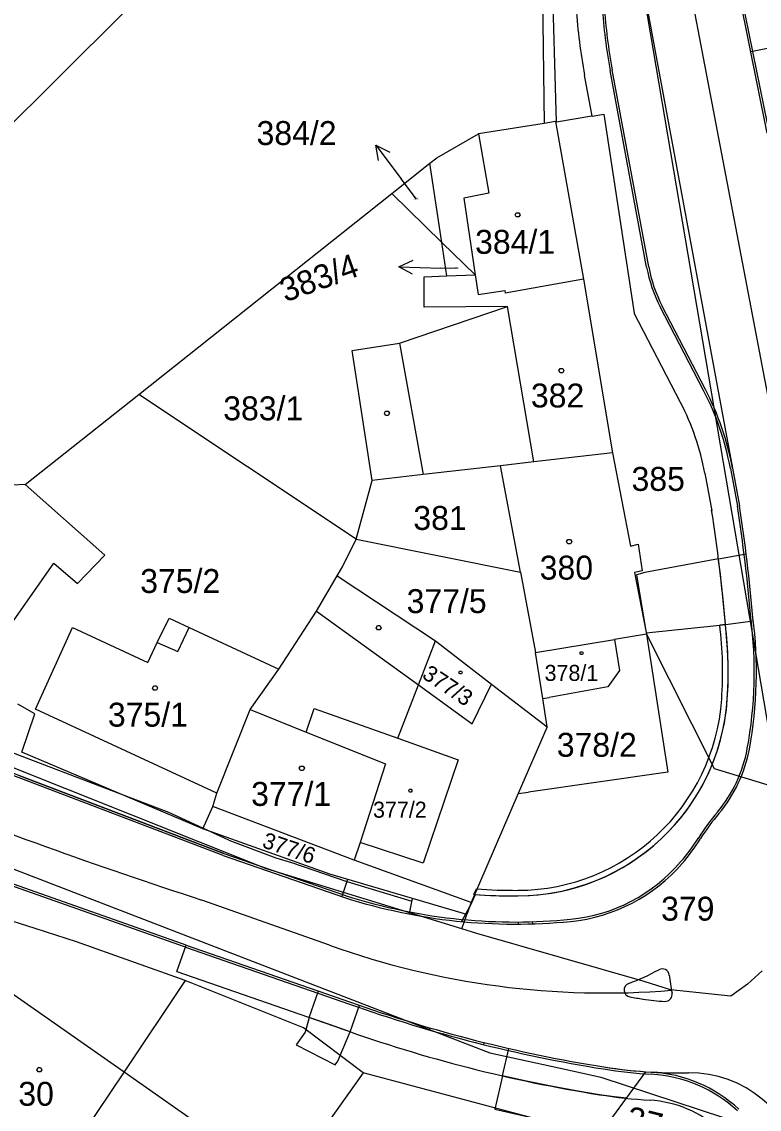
# Model space of a CAD drawing. Extents: x -639621 to -639329, y -1192893 to -1192488.
# Drawn here: x -639553.5 to -639501.1, y -1192724.9 to -1192647.6 of the extents above; entities that cross this region are included whole.
import ezdxf

# ---------------------------------------------------------------- set-up
doc = ezdxf.new("R2010")
doc.units = 0
for name, color, linetype in [('Vrstva 1', 7, 'Continuous'), ('Vrstva 19', 7, 'Continuous'), ('Vrstva 2', 7, 'Continuous'), ('Vrstva 20', 7, 'Continuous'), ('Vrstva 22', 7, 'Continuous'), ('Vrstva 4', 7, 'Continuous'), ('Vrstva 5', 7, 'Continuous'), ('Vrstva 7', 7, 'Continuous')]:
    doc.layers.add(name, color=color, linetype=linetype)

msp = doc.modelspace()

# ---------------------------------------------------------------- linework, layer by layer
at = {"layer": 'Vrstva 1'}
for p, q in [((-639516.92, -1192617.59), (-639516.39, -1192654.83)), ((-639499.71, -1192702.08), (-639511.27, -1192634.08)), ((-639559.67, -1192660.27), (-639546.32, -1192646.99)), ((-639516.39, -1192654.83), (-639521.06, -1192655.58)), ((-639515.58, -1192654.7), (-639516.39, -1192654.83)), ((-639515.58, -1192654.7), (-639513.58, -1192665.9)), ((-639524.03, -1192657.28), (-639521.06, -1192655.58)), ((-639524.51, -1192657.66), (-639524.03, -1192657.28)), ((-639527.23, -1192659.81), (-639524.51, -1192657.66)), ((-639523.66, -1192663.29), (-639524.51, -1192657.66)), ((-639545.2, -1192674.09), (-639527.23, -1192659.81)), ((-639523.66, -1192663.29), (-639527.23, -1192659.81)), ((-639523.66, -1192663.29), (-639521.3, -1192665.59)), ((-639523.3, -1192665.67), (-639523.66, -1192663.29)), ((-639524.92, -1192665.73), (-639523.3, -1192665.67)), ((-639524.91, -1192667.89), (-639524.92, -1192665.73)), ((-639523.3, -1192665.67), (-639521.3, -1192665.59)), ((-639521.3, -1192665.59), (-639521.09, -1192666.98)), ((-639513.58, -1192665.9), (-639519.15, -1192666.89)), ((-639513.58, -1192665.9), (-639511.54, -1192678.25)), ((-639521.09, -1192666.98), (-639519.18, -1192666.7)), ((-639519.18, -1192666.7), (-639519.15, -1192666.89)), ((-639526.67, -1192670.46), (-639518.99, -1192667.84)), ((-639518.99, -1192667.84), (-639524.91, -1192667.89)), ((-639530.04, -1192670.97), (-639526.67, -1192670.46)), ((-639528.62, -1192680.2), (-639530.04, -1192670.97)), ((-639553.28, -1192680.5), (-639545.2, -1192674.09)), ((-639529.75, -1192684.37), (-639545.2, -1192674.09)), ((-639511.54, -1192678.25), (-639517.13, -1192678.89)), ((-639511.54, -1192678.25), (-639510.25, -1192684.87)), ((-639517.13, -1192678.89), (-639519.5, -1192679.16)), ((-639525, -1192679.79), (-639528.62, -1192680.2)), ((-639519.5, -1192679.16), (-639525, -1192679.79)), ((-639518.08, -1192686.72), (-639519.5, -1192679.16)), ((-639553.28, -1192680.5), (-639555.06, -1192680.58)), ((-639547.62, -1192685.52), (-639553.28, -1192680.5)), ((-639529.75, -1192684.37), (-639528.62, -1192680.2)), ((-639530.73, -1192686.34), (-639529.75, -1192684.37)), ((-639529.75, -1192684.37), (-639518.08, -1192686.72)), ((-639510.25, -1192684.87), (-639509.7, -1192684.74)), ((-639509.7, -1192684.74), (-639509.43, -1192686.62)), ((-639554.62, -1192690.9), (-639551.25, -1192686.09)), ((-639551.25, -1192686.09), (-639549.57, -1192687.53)), ((-639549.57, -1192687.53), (-639547.62, -1192685.52)), ((-639531.11, -1192686.99), (-639530.73, -1192686.34)), ((-639518.08, -1192686.72), (-639517.01, -1192692.43)), ((-639509.43, -1192686.62), (-639509.96, -1192686.74)), ((-639509.96, -1192686.74), (-639509.12, -1192691.12)), ((-639532.58, -1192689.5), (-639531.11, -1192686.99)), ((-639531.11, -1192686.99), (-639524.12, -1192691.61)), ((-639535.25, -1192693.61), (-639532.58, -1192689.5)), ((-639552.55, -1192696.45), (-639549.92, -1192690.66)), ((-639549.92, -1192690.66), (-639544.58, -1192693.13)), ((-639543.9, -1192691.72), (-639543.06, -1192690)), ((-639543.06, -1192690), (-639541.63, -1192690.66)), ((-639541.63, -1192690.66), (-639535.25, -1192693.61)), ((-639517.01, -1192692.43), (-639511.39, -1192691.5)), ((-639509.12, -1192691.12), (-639511.39, -1192691.5)), ((-639511.39, -1192691.5), (-639511.04, -1192693.7)), ((-639509.12, -1192691.12), (-639504.3, -1192700.68)), ((-639509.12, -1192691.12), (-639507.59, -1192700.94)), ((-639544.58, -1192693.13), (-639543.9, -1192691.72)), ((-639525.33, -1192694.73), (-639524.12, -1192691.61)), ((-639524.12, -1192691.61), (-639520.13, -1192694.67)), ((-639516.49, -1192695.7), (-639517.01, -1192692.43)), ((-639537.29, -1192696.49), (-639535.25, -1192693.61)), ((-639511.04, -1192693.7), (-639511.86, -1192694.86)), ((-639526.8, -1192698.52), (-639525.33, -1192694.73)), ((-639520.13, -1192694.67), (-639516.17, -1192697.71)), ((-639511.86, -1192694.86), (-639516.03, -1192695.62)), ((-639552.6, -1192696.8), (-639553.81, -1192696.1)), ((-639516.49, -1192695.7), (-639516.03, -1192695.62)), ((-639516.17, -1192697.71), (-639516.49, -1192695.7)), ((-639553.52, -1192699.51), (-639552.6, -1192696.8)), ((-639539.66, -1192702.42), (-639552.55, -1192696.45)), ((-639539.66, -1192702.42), (-639537.29, -1192696.49)), ((-639533.3, -1192698.08), (-639532.75, -1192696.42)), ((-639532.75, -1192696.42), (-639526.8, -1192698.52)), ((-639533.3, -1192698.08), (-639527.66, -1192700.33)), ((-639516.17, -1192697.71), (-639518.23, -1192702.46)), ((-639526.8, -1192698.52), (-639522.5, -1192700.06)), ((-639536.13, -1192707.8), (-639556.03, -1192699.88)), ((-639540.65, -1192704.97), (-639553.52, -1192699.51)), ((-639527.66, -1192700.33), (-639529.47, -1192705.92)), ((-639522.5, -1192700.06), (-639524.99, -1192707.41)), ((-639504.3, -1192700.68), (-639499.71, -1192702.08)), ((-639507.59, -1192700.94), (-639517.51, -1192702.36)), ((-639539.95, -1192703.37), (-639539.66, -1192702.42)), ((-639518.23, -1192702.46), (-639521.59, -1192710.19)), ((-639518.23, -1192702.46), (-639517.51, -1192702.36)), ((-639540.65, -1192704.97), (-639539.95, -1192703.37)), ((-639529.9, -1192707.18), (-639539.95, -1192703.37)), ((-639531.62, -1192708.19), (-639540.65, -1192704.97)), ((-639529.47, -1192705.92), (-639529.9, -1192707.18)), ((-639524.99, -1192707.41), (-639529.47, -1192705.92)), ((-639555.84, -1192707.16), (-639520.25, -1192720.87)), ((-639521.59, -1192710.19), (-639529.9, -1192707.18)), ((-639522.25, -1192712.07), (-639536.13, -1192707.8)), ((-639521.89, -1192711.04), (-639531.62, -1192708.19)), ((-639552.59, -1192712.04), (-639559.39, -1192709.9)), ((-639521.59, -1192710.19), (-639521.89, -1192711.04)), ((-639522.25, -1192712.07), (-639521.89, -1192711.04)), ((-639549.63, -1192713), (-639552.59, -1192712.04)), ((-639521.18, -1192712.4), (-639522.25, -1192712.07)), ((-639541.91, -1192715.74), (-639549.63, -1192713)), ((-639509.27, -1192715.82), (-639521.18, -1192712.4)), ((-639500.89, -1192715.05), (-639501.93, -1192716.01)), ((-639541.91, -1192715.74), (-639546.26, -1192722.22)), ((-639533.5, -1192719.11), (-639541.91, -1192715.74)), ((-639507.41, -1192716.4), (-639509.27, -1192715.82)), ((-639501.93, -1192716.01), (-639503.12, -1192716.84)), ((-639503.12, -1192716.84), (-639507.41, -1192716.4)), ((-639529.26, -1192722.31), (-639533.5, -1192719.11)), ((-639520.25, -1192720.87), (-639514.8, -1192722.07)), ((-639546.26, -1192722.22), (-639553.6, -1192733.16)), ((-639529.26, -1192722.31), (-639534.88, -1192730.18)), ((-639515.75, -1192725.9), (-639529.26, -1192722.31)), ((-639514.8, -1192722.07), (-639512.37, -1192722.6)), ((-639512.37, -1192722.6), (-639501.84, -1192726.06))]:
    msp.add_line(p, q, dxfattribs=at)
at = {"layer": 'Vrstva 19'}
for p, q in [((-639500.522, -1192655.528), (-639503.63, -1192640.243)), ((-639510.022, -1192641.421), (-639503.547, -1192676.41)), ((-639508.955, -1192665.025), (-639511.547, -1192651.035)), ((-639504.915, -1192673.752), (-639507.999, -1192667.81)), ((-639503.547, -1192676.41), (-639503.002, -1192679.321)), ((-639503.002, -1192679.321), (-639502.504, -1192682.009)), ((-639503.504, -1192690.429), (-639503.901, -1192690.477)), ((-639553.675, -1192701.206), (-639539.167, -1192706.72)), ((-639541.902, -1192713.36), (-639564.856, -1192705.277)), ((-639539.22, -1192706.86), (-639530.574, -1192709.843)), ((-639518.204, -1192711.73), (-639518.205, -1192711.58)), ((-639517.204, -1192711.712), (-639517.208, -1192711.562)), ((-639541.852, -1192713.218), (-639530.17, -1192717.267))]:
    msp.add_line(p, q, dxfattribs=at)
for points in [[(-639498.81, -1192682.926), (-639506.825, -1192640.839)], [(-639539.22, -1192706.86), (-639553.728, -1192701.346), (-639557.98, -1192699.73), (-639562.836, -1192697.903), (-639564.75, -1192697.41), (-639568.873, -1192696.511), (-639573.54, -1192695.73), (-639576.6, -1192695.68)], [(-639541.852, -1192713.218), (-639564.809, -1192705.135), (-639568.527, -1192703.984), (-639572.572, -1192703.272), (-639576.59, -1192703), (-639577.11, -1192703.02), (-639578.368, -1192703.481), (-639579, -1192703.481), (-639579.02, -1192702.96), (-639581.467, -1192703.299)], [(-639531.66, -1192713.229), (-639540.72, -1192710.021)]]:
    msp.add_lwpolyline(points, dxfattribs=at)
for centre, radius, start, end in [((-639472.216, -1192643.75), 40, 183.95854, 190.49396), ((-639499.123, -1192663.204), 10, 190.49396, 207.42516), ((-639522.667, -1192682.964), 20, 10.49394, 27.42516), ((-639611.673, -1192699.173), 110.51, 4.78995, 8.93561), ((-639531.297, -1192693.822), 30, 349.4986, 7.42356), ((-639511.632, -1192697.467), 10, 320.11865, 349.4986), ((-639433.012, -1192376.653), 350.335, 248.24655, 252.09481), ((-639492.583, -1192713.657), 15, 139.31944, 147.7483), ((-639517.951, -1192697.64), 15, 319.34477, 327.71659), ((-639515.675, -1192699.595), 12, 275.6507, 319.34477), ((-639518.432, -1192671.731), 40, 252.32913, 275.6507), ((-639512.074, -1192658.483), 58.143, 250.31441, 274.68016), ((-639516.023, -1192700.666), 16.289, 290.27868, 298.58822), ((-639507.989, -1192715.409), 0.5, 6.46718, 118.58822), ((-639492.588, -1192713.663), 15, 186.46718, 191.39098), ((-639510.204, -1192716.415), 0.5, 110.27868, 260.61676), ((-639453.766, -1192373.81), 347.722, 260.6455, 260.80232), ((-639507.783, -1192716.724), 0.5, 266.73375, 11.39098), ((-639496.485, -1192623.111), 100, 250.31486, 260.98854), ((-639506.892, -1192701.125), 16.125, 261.1699, 266.73375), ((-639506.666, -1192687.309), 35, 260.98854, 270.86714), ((-639506.666, -1192687.309), 35, 260.98854, 266.6063), ((-639509.33, -1192732.23), 10, 47.24867, 86.6063), ((-639506.015, -1192730.304), 8, 9.47307, 90.86714)]:
    msp.add_arc(centre, radius, start, end, dxfattribs=at)
at = {"layer": 'Vrstva 20'}
for p, q in [((-639500.248, -1192656.125), (-639503.483, -1192640.213)), ((-639500.159, -1192649.442), (-639501.697, -1192649.752)), ((-639509.103, -1192665.053), (-639511.694, -1192651.063)), ((-639512.972, -1192654.32), (-639513.513, -1192651.4)), ((-639505.048, -1192673.821), (-639508.132, -1192667.879)), ((-639506.69, -1192674.673), (-639509.985, -1192668.324)), ((-639504.969, -1192679.686), (-639504.471, -1192682.373)), ((-639503.149, -1192679.349), (-639502.652, -1192682.036)), ((-639503.994, -1192685.776), (-639502.023, -1192685.41)), ((-639503.504, -1192690.429), (-639501.518, -1192690.187)), ((-639539.171, -1192706.718), (-639530.525, -1192709.701)), ((-639530.41, -1192708.71), (-639530.777, -1192709.773)), ((-639530.41, -1192708.71), (-639525.806, -1192710.1)), ((-639521.381, -1192709.616), (-639521.21, -1192709.228)), ((-639525.766, -1192709.905), (-639525.985, -1192710.988)), ((-639521.531, -1192710.19), (-639522.258, -1192711.547)), ((-639542.507, -1192715.108), (-639541.852, -1192713.218)), ((-639541.901, -1192713.36), (-639530.219, -1192717.409)), ((-639542.507, -1192715.108), (-639530.825, -1192719.157)), ((-639533.095, -1192718.37), (-639532.44, -1192716.48)), ((-639530.188, -1192719.382), (-639529.528, -1192717.494)), ((-639533.095, -1192718.37), (-639533.331, -1192719.238)), ((-639531.642, -1192718.876), (-639533.095, -1192718.37)), ((-639530.188, -1192719.382), (-639531.642, -1192718.876)), ((-639524.524, -1192719.099), (-639524.566, -1192719.243)), ((-639530.899, -1192721.073), (-639530.188, -1192719.382)), ((-639520.662, -1192720.144), (-639520.698, -1192720.29)), ((-639519.358, -1192722.513), (-639518.909, -1192720.564)), ((-639510.539, -1192724.105), (-639509.151, -1192722.22))]:
    msp.add_line(p, q, dxfattribs=at)
for points in [[(-639512.972, -1192654.32), (-639512.15, -1192654.18), (-639509.985, -1192668.324)], [(-639521.53, -1192710.19), (-639521.279, -1192709.624), (-639520.578, -1192709.67), (-639519.578, -1192709.713), (-639518.49, -1192709.731), (-639517.435, -1192709.704), (-639516.65, -1192709.636), (-639515.866, -1192709.527), (-639515.106, -1192709.38), (-639514.329, -1192709.187), (-639513.468, -1192708.921), (-639512.701, -1192708.635), (-639512.036, -1192708.347), (-639511.296, -1192707.98), (-639510.616, -1192707.595), (-639509.882, -1192707.126), (-639509.227, -1192706.653), (-639508.714, -1192706.244), (-639508.076, -1192705.679), (-639507.517, -1192705.127), (-639507.038, -1192704.606), (-639506.576, -1192704.051), (-639506.038, -1192703.328), (-639505.523, -1192702.541), (-639505.08, -1192701.762), (-639504.715, -1192701.028), (-639504.372, -1192700.227), (-639504.087, -1192699.438), (-639503.815, -1192698.516), (-639503.574, -1192697.428), (-639503.418, -1192696.361), (-639503.341, -1192695.375), (-639503.305, -1192694.463), (-639503.303, -1192693.269), (-639503.345, -1192692.185), (-639503.44, -1192691.002), (-639503.504, -1192690.429)], [(-639543.079, -1192703.789), (-639553.195, -1192699.944), (-639557.449, -1192698.327), (-639562.383, -1192696.471), (-639564.402, -1192695.95), (-639568.589, -1192695.038), (-639573.403, -1192694.232), (-639573.649, -1192695.728)], [(-639539.167, -1192706.72), (-639553.675, -1192701.206), (-639557.927, -1192699.59), (-639562.791, -1192697.76), (-639564.715, -1192697.264), (-639568.845, -1192696.364), (-639573.526, -1192695.58), (-639573.624, -1192695.579)], [(-639538.8, -1192705.755), (-639543.079, -1192703.789)], [(-639538.8, -1192705.755), (-639535.47, -1192707.02), (-639534.36, -1192707.36), (-639530.41, -1192708.71)], [(-639530.41, -1192708.71), (-639530.357, -1192708.56)]]:
    msp.add_lwpolyline(points, dxfattribs=at)
for points in [[(-639503.994, -1192685.776), (-639509.24, -1192686.75), (-639509.83, -1192686.92), (-639509.13, -1192691.04), (-639503.901, -1192690.477), (-639503.504, -1192690.429), (-639503.762, -1192687.758)], [(-639519.358, -1192722.513), (-639519.9, -1192724.87), (-639515.62, -1192725.85), (-639512.469, -1192726.756), (-639510.539, -1192724.105), (-639511.377, -1192723.998), (-639512.461, -1192723.852), (-639514.111, -1192723.576), (-639515.895, -1192723.247), (-639517.764, -1192722.866)]]:
    msp.add_lwpolyline(points, close=True, dxfattribs=at)
for centre, radius, start, end in [((-639472.216, -1192643.75), 42, 183.95854, 190.49396), ((-639472.216, -1192643.75), 40.15, 183.95854, 190.49396), ((-639499.123, -1192663.204), 10.15, 190.49396, 207.42516), ((-639522.667, -1192682.964), 19.85, 10.49394, 27.42516), ((-639522.667, -1192682.964), 18, 10.49394, 27.42516), ((-639611.673, -1192699.173), 110.36, 4.78995, 8.93561), ((-639620.557, -1192700.406), 117.478, 4.87204, 8.85649), ((-639531.297, -1192693.822), 27.6, 355.99178, 6.96025), ((-639531.297, -1192693.822), 28, 355.99178, 6.96042), ((-639531.297, -1192693.822), 29.85, 349.4986, 7.42356), ((-639518.329, -1192694.73), 14.6, 270.25546, 355.99178), ((-639518.329, -1192694.73), 15, 270.25546, 355.99178), ((-639511.632, -1192697.467), 9.85, 320.11865, 349.4986), ((-639492.583, -1192713.657), 15.15, 139.31944, 147.7483), ((-639517.951, -1192697.64), 14.85, 319.34477, 327.71659), ((-639515.675, -1192699.595), 11.85, 275.6507, 319.34477), ((-639518.432, -1192671.731), 37.6, 265.76257, 270.25546), ((-639518.432, -1192671.731), 39.85, 252.32913, 264.45054), ((-639518.432, -1192671.731), 38, 265.54892, 270.25546), ((-639518.432, -1192671.731), 39.85, 264.45054, 275.6507), ((-639496.485, -1192623.111), 100.15, 250.31486, 260.98854), ((-639496.485, -1192623.111), 102, 250.31486, 260.98854), ((-639506.666, -1192687.309), 35.15, 260.98854, 266.6063), ((-639509.33, -1192732.23), 9.85, 47.24867, 86.6063), ((-639506.666, -1192687.309), 37, 260.98854, 266.6063), ((-639509.33, -1192732.23), 8, 47.24867, 86.6063)]:
    msp.add_arc(centre, radius, start, end, dxfattribs=at)
at = {"layer": 'Vrstva 22'}
for p, q in [((-639533.331, -1192719.238), (-639533.38, -1192719.42)), ((-639533.38, -1192719.42), (-639534.03, -1192720.31)), ((-639534.03, -1192720.31), (-639531.258, -1192721.726)), ((-639531.258, -1192721.726), (-639531.07, -1192721.48)), ((-639531.07, -1192721.48), (-639530.899, -1192721.073))]:
    msp.add_line(p, q, dxfattribs=at)
msp.add_lwpolyline([(-639513.004, -1192654.325), (-639515.5, -1192654.75), (-639516.434, -1192622.323)], dxfattribs=at)
at = {"layer": 'Vrstva 4'}
for p, q in [((-639521.06, -1192655.58), (-639520.33, -1192659.8)), ((-639520.33, -1192659.8), (-639522.11, -1192660.14)), ((-639522.11, -1192660.14), (-639521.3, -1192665.59)), ((-639517.13, -1192678.89), (-639518.99, -1192667.84)), ((-639526.67, -1192670.46), (-639525, -1192679.79)), ((-639532.58, -1192689.5), (-639525.33, -1192694.73)), ((-639542.44, -1192692.36), (-639541.63, -1192690.66)), ((-639543.9, -1192691.72), (-639542.44, -1192692.36)), ((-639525.33, -1192694.73), (-639521.51, -1192697.49)), ((-639521.51, -1192697.49), (-639520.13, -1192694.67)), ((-639537.29, -1192696.49), (-639533.3, -1192698.08)), ((-639559.48, -1192712.99), (-639546.26, -1192722.22)), ((-639546.26, -1192722.22), (-639534.88, -1192730.18))]:
    msp.add_line(p, q, dxfattribs=at)
at = {"layer": 'Vrstva 5'}
for points in [[(-639518.19, -1192661.18), (-639518.1, -1192661.33), (-639518.19, -1192661.48), (-639518.37, -1192661.48), (-639518.46, -1192661.33), (-639518.37, -1192661.18)], [(-639515.07, -1192672.25), (-639514.98, -1192672.4), (-639515.07, -1192672.55), (-639515.25, -1192672.55), (-639515.34, -1192672.4), (-639515.25, -1192672.25)], [(-639527.48, -1192675.28), (-639527.39, -1192675.43), (-639527.48, -1192675.58), (-639527.66, -1192675.58), (-639527.75, -1192675.43), (-639527.66, -1192675.28)], [(-639514.52, -1192684.4), (-639514.43, -1192684.55), (-639514.52, -1192684.7), (-639514.7, -1192684.7), (-639514.79, -1192684.55), (-639514.7, -1192684.4)], [(-639528.07, -1192690.52), (-639527.98, -1192690.67), (-639528.07, -1192690.82), (-639528.25, -1192690.82), (-639528.34, -1192690.67), (-639528.25, -1192690.52)], [(-639513.67, -1192692.38), (-639513.609, -1192692.48), (-639513.67, -1192692.58), (-639513.79, -1192692.58), (-639513.851, -1192692.48), (-639513.79, -1192692.38)], [(-639522.27, -1192693.75), (-639522.209, -1192693.85), (-639522.27, -1192693.95), (-639522.39, -1192693.95), (-639522.451, -1192693.85), (-639522.39, -1192693.75)], [(-639543.96, -1192694.81), (-639543.87, -1192694.96), (-639543.96, -1192695.11), (-639544.14, -1192695.11), (-639544.23, -1192694.96), (-639544.14, -1192694.81)], [(-639533.53, -1192700.51), (-639533.44, -1192700.66), (-639533.53, -1192700.81), (-639533.71, -1192700.81), (-639533.8, -1192700.66), (-639533.71, -1192700.51)], [(-639525.84, -1192702.15), (-639525.779, -1192702.25), (-639525.84, -1192702.35), (-639525.96, -1192702.35), (-639526.021, -1192702.25), (-639525.96, -1192702.15)], [(-639552.19, -1192721.93), (-639552.1, -1192722.08), (-639552.19, -1192722.23), (-639552.37, -1192722.23), (-639552.46, -1192722.08), (-639552.37, -1192721.93)]]:
    msp.add_lwpolyline(points, close=True, dxfattribs=at)
at = {"layer": 'Vrstva 7'}
for p, q in [((-639528.361, -1192656.371), (-639526.56, -1192658.77)), ((-639525.47, -1192660.22), (-639526.56, -1192658.77)), ((-639526.729, -1192665.018), (-639523.73, -1192665.11)), ((-639522.57, -1192665.15), (-639523.73, -1192665.11))]:
    msp.add_line(p, q, dxfattribs=at)
for points in [[(-639528.161, -1192657.471), (-639528.361, -1192656.371), (-639527.361, -1192656.87)], [(-639525.744, -1192665.548), (-639526.729, -1192665.018), (-639525.714, -1192664.549)]]:
    msp.add_lwpolyline(points, dxfattribs=at)

# ---------------------------------------------------------------- texts
at = {"layer": 'Vrstva 2'}
for s, height, p in [('384/2', 0.1, (-639525.683, -1192660.22)), ('384/1', 1.7, (-639521.299, -1192664.1)), ('383/4', 0.1, (-639522.784, -1192665.15)), ('382', 1.7, (-639517.332, -1192675.02)), ('383/1', 1.7, (-639539.206, -1192675.93)), ('385', 1.7, (-639510.175, -1192680.946)), ('381', 1.7, (-639525.69, -1192683.72)), ('380', 1.7, (-639516.705, -1192687.25)), ('375/2', 1.7, (-639545.111, -1192688.2)), ('377/5', 1.7, (-639526.167, -1192689.63)), ('378/1', 1.14, (-639516.358, -1192694.45)), ('375/1', 1.7, (-639547.409, -1192697.7)), ('378/2', 1.7, (-639515.49, -1192699.84)), ('377/1', 1.7, (-639537.222, -1192703.33)), ('377/2', 1.14, (-639528.556, -1192704.17)), ('379', 1.7, (-639508.072, -1192711.483)), ('30', 1.7, (-639553.779, -1192724.64))]:
    msp.add_text(s, height=height, dxfattribs=at).set_placement(p)
for s, height, rotation, p in [('377/3', 1.14, 326.41406, (-639525.14, -1192694.192)), ('377/6', 1.14, 341.42555, (-639536.507, -1192706.255)), ('374', 1.7, 346.20913, (-639510.682, -1192726.291))]:
    msp.add_text(s, height=height, rotation=rotation, dxfattribs=at).set_placement(p)
at = {"layer": 'Vrstva 7'}
msp.add_text('384/2', height=1.7, dxfattribs=at).set_placement((-639536.839, -1192656.37))
msp.add_text('383/4', height=1.7, rotation=19.76704, dxfattribs=at).set_placement((-639534.794, -1192667.558))

doc.saveas('drawing.dxf')
